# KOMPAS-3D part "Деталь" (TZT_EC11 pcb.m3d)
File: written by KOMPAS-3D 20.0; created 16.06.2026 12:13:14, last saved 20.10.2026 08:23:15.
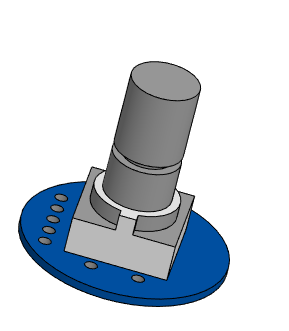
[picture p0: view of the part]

Document properties: Полное имя файла: D:\RicWork\Project-EPS32\box_compas\переключатели и кнопки\TZT_EC11 pcb.m3d

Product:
- Part/product: Деталь
    Материал: Фторопласт-4  ГОСТ 10007-80 Е (density 2200 kg/m3)
    Масса: 0.00435205

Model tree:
1. Эскиз:1
2. Элемент выдавливания:1
     Расстояние 1 = 1
3. Эскиз:2  (with: Элемент выдавливания:1)
4. Элемент выдавливания:2
     Расстояние 1 = 6.5
5. Эскиз:3  (with: Элемент выдавливания:2)
6. Элемент выдавливания:3
     Расстояние 1 = 5
7. Эскиз:4  (with: Элемент выдавливания:3)
8. Эскиз:6  (with: Элемент выдавливания:1)
9. Элемент выдавливания:6
     Расстояние 2 = 12.5
10. Массив по сетке:1  (with: Эскиз:6, Элемент выдавливания:1, Элемент выдавливания:6)  (labels: v168_1_2_v148; v168_1_2_v149; v168_1_2_v150; Толщина стенки 1)  (5 pattern instances)
     Шаг 1 = 10; Угол раствора = -90; Шаг 2 = 2.54
11. Элемент выдавливания:7
     Расстояние 1 = 1
12. Эскиз:7  (with: Элемент выдавливания:7)
13. Элемент выдавливания:8
     Расстояние 1 = 9
14. Эскиз:8  (with: Элемент выдавливания:1)
15. Элемент выдавливания:9  (with: Массив по сетке:1, Эскиз:8, Элемент выдавливания:2)  (3 pattern instances)
     Расстояние 2 = 2; Шаг 1 = 2.54; Угол раствора = 90; Шаг 2 = 10
16. Эскиз:9  (with: Элемент выдавливания:2, Элемент выдавливания:3)
17. Элемент выдавливания:10
     Расстояние 2 = 2
18. Эскиз:10  (with: Элемент выдавливания:1, Элемент выдавливания:9)
19. Элемент выдавливания:11
     Расстояние 2 = 22.5
20. Массив по сетке:2  (with: Элемент выдавливания:11, Эскиз:10, Элемент выдавливания:10)  (2 pattern instances)
     Шаг 1 = 5.5; Угол раствора = 90
21. Эскиз:11  (with: Элемент выдавливания:1, Элемент выдавливания:9, Элемент выдавливания:11)  (labels: Фторопласт-4  ГОСТ 10007-80 Е)

Referenced files in D:\myProjects\Progect_esp32\box_compas\: Rotary Encoder Module SAMIORE ROBOT.png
